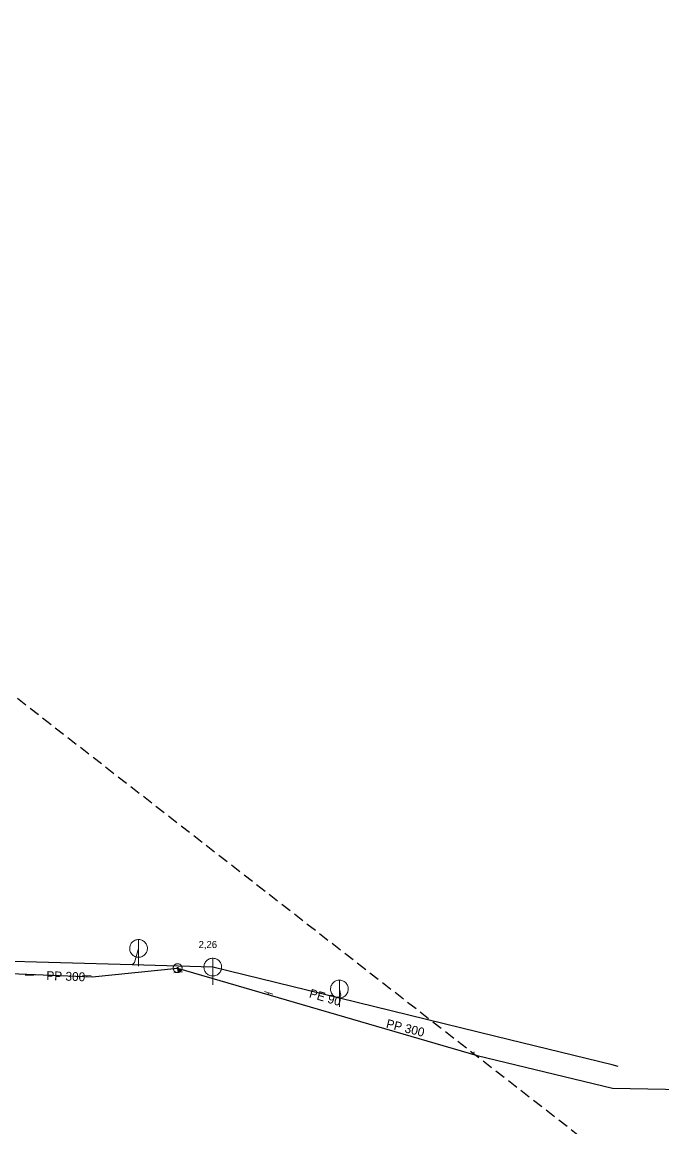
# Model space of a CAD drawing. Extents: x -683466 to -682479, y -996772 to -995963.
# Drawn here: x -683237.4 to -683165.2, y -996087.9 to -995963.2 of the extents above; entities that cross this region are included whole.
import ezdxf

# ---------------------------------------------------------------- set-up
doc = ezdxf.new("R2010")
doc.units = 0
doc.header["$LTSCALE"] = 0.4
doc.linetypes.add('MEDIUM_DASHED', pattern=[4.5, 3, -1.5])
doc.layers.add('1', color=7, linetype='Continuous')
for name, color, linetype, lineweight in [('11', 7, 'Continuous', 13), ('14', 7, 'Continuous', 25), ('17', 7, 'Continuous', 25), ('22', 7, 'Continuous', 13), ('34', 7, 'Continuous', 13), ('47', 7, 'Continuous', 13), ('63', 7, 'MEDIUM_DASHED', 25), ('9', 7, 'Continuous', 13)]:
    doc.layers.add(name, color=color, linetype=linetype, lineweight=lineweight)

msp = doc.modelspace()

# ---------------------------------------------------------------- linework, layer by layer
at = {"layer": '11'}
for points in [[(-683224.3, -996067.739), (-683224.741, -996069.322), (-683225.026, -996069.59)], [(-683201.629, -996072.32), (-683201.464, -996073), (-683201.638, -996073.349)]]:
    msp.add_lwpolyline(points, dxfattribs=at)
at = {"layer": '14', "lineweight": 13}
for p, q in [((-683236.581, -996070.672), (-683236.579, -996070.77)), ((-683230.13, -996070.936), (-683230.129, -996070.809)), ((-683209.68, -996072.941), (-683209.62, -996072.75)), ((-683186.522, -996079.702), (-683186.44, -996079.399))]:
    msp.add_line(p, q, dxfattribs=at)
at = {"layer": '14'}
for points in [[(-683215.92, -996069.85), (-683225.026, -996069.59), (-683241.213, -996069.127), (-683247.399, -996068.949)], [(-683170.17, -996081.059), (-683170.859, -996080.89), (-683183.962, -996077.681), (-683201.638, -996073.349), (-683215.92, -996069.85)]]:
    msp.add_lwpolyline(points, dxfattribs=at)
at = {"layer": '14', "lineweight": 13}
msp.add_lwpolyline([(-683219.888, -996069.96), (-683219.831, -996070.447), (-683219.681, -996070.181)], dxfattribs=at)
at = {"layer": '17'}
for points in [[(-683345.87, -996001.27), (-683340.96, -996022.3), (-683339.832, -996025.943), (-683304.056, -996053.017), (-683282.79, -996067.766), (-683274.905, -996069.189), (-683269.5, -996070.27), (-683248.91, -996070.167), (-683229.542, -996070.96), (-683219.888, -996069.96)], [(-683219.888, -996069.96), (-683186.097, -996079.826), (-683170.817, -996083.517), (-683164.824, -996083.636), (-683139.583, -996085.59), (-683125.156, -996084.857)]]:
    msp.add_lwpolyline(points, dxfattribs=at)
at = {"layer": '22'}
for p, q in [((-683224.3, -996069.739), (-683224.299, -996066.739)), ((-683215.92, -996071.85), (-683215.919, -996068.85)), ((-683201.629, -996074.32), (-683201.628, -996071.32))]:
    msp.add_line(p, q, dxfattribs=at)
for points in [[(-683223.3, -996067.739), (-683223.305, -996067.63), (-683223.323, -996067.522), (-683223.353, -996067.416), (-683223.393, -996067.315), (-683223.445, -996067.218), (-683223.507, -996067.128), (-683223.579, -996067.045), (-683223.659, -996066.971), (-683223.747, -996066.905), (-683223.841, -996066.85), (-683223.941, -996066.805), (-683224.046, -996066.772), (-683224.153, -996066.75), (-683224.262, -996066.74), (-683224.372, -996066.742), (-683224.48, -996066.756), (-683224.587, -996066.781), (-683224.69, -996066.818), (-683224.788, -996066.867), (-683224.88, -996066.925), (-683224.966, -996066.994), (-683225.043, -996067.071), (-683225.112, -996067.157), (-683225.171, -996067.249), (-683225.219, -996067.347), (-683225.256, -996067.45), (-683225.282, -996067.557), (-683225.296, -996067.665), (-683225.299, -996067.775), (-683225.289, -996067.884), (-683225.268, -996067.991), (-683225.234, -996068.095), (-683225.19, -996068.195), (-683225.135, -996068.29), (-683225.069, -996068.378), (-683224.995, -996068.458), (-683224.912, -996068.53), (-683224.822, -996068.592), (-683224.726, -996068.644), (-683224.624, -996068.685), (-683224.519, -996068.715), (-683224.411, -996068.733), (-683224.301, -996068.739), (-683224.192, -996068.733), (-683224.084, -996068.715), (-683223.979, -996068.686), (-683223.877, -996068.645), (-683223.78, -996068.593), (-683223.69, -996068.531), (-683223.607, -996068.46), (-683223.532, -996068.38), (-683223.467, -996068.292), (-683223.411, -996068.198), (-683223.367, -996068.098), (-683223.333, -996067.994), (-683223.311, -996067.886), (-683223.301, -996067.777)], [(-683214.92, -996069.85), (-683214.925, -996069.741), (-683214.943, -996069.633), (-683214.973, -996069.527), (-683215.013, -996069.426), (-683215.065, -996069.329), (-683215.127, -996069.239), (-683215.199, -996069.156), (-683215.279, -996069.082), (-683215.367, -996069.016), (-683215.461, -996068.961), (-683215.561, -996068.916), (-683215.666, -996068.883), (-683215.773, -996068.861), (-683215.882, -996068.851), (-683215.992, -996068.853), (-683216.1, -996068.867), (-683216.207, -996068.892), (-683216.31, -996068.929), (-683216.408, -996068.978), (-683216.5, -996069.036), (-683216.586, -996069.105), (-683216.663, -996069.182), (-683216.732, -996069.268), (-683216.791, -996069.36), (-683216.839, -996069.458), (-683216.876, -996069.561), (-683216.902, -996069.668), (-683216.916, -996069.776), (-683216.919, -996069.886), (-683216.909, -996069.995), (-683216.888, -996070.102), (-683216.854, -996070.206), (-683216.81, -996070.306), (-683216.755, -996070.401), (-683216.689, -996070.489), (-683216.615, -996070.569), (-683216.532, -996070.641), (-683216.442, -996070.703), (-683216.346, -996070.755), (-683216.244, -996070.796), (-683216.139, -996070.826), (-683216.031, -996070.844), (-683215.921, -996070.85), (-683215.812, -996070.844), (-683215.704, -996070.826), (-683215.599, -996070.797), (-683215.497, -996070.756), (-683215.4, -996070.704), (-683215.31, -996070.642), (-683215.227, -996070.571), (-683215.152, -996070.491), (-683215.087, -996070.403), (-683215.031, -996070.309), (-683214.987, -996070.209), (-683214.953, -996070.105), (-683214.931, -996069.997), (-683214.921, -996069.888)], [(-683200.629, -996072.32), (-683200.634, -996072.211), (-683200.652, -996072.103), (-683200.682, -996071.997), (-683200.722, -996071.896), (-683200.774, -996071.799), (-683200.836, -996071.709), (-683200.908, -996071.626), (-683200.988, -996071.552), (-683201.076, -996071.486), (-683201.17, -996071.431), (-683201.27, -996071.386), (-683201.375, -996071.353), (-683201.482, -996071.331), (-683201.591, -996071.321), (-683201.701, -996071.323), (-683201.809, -996071.337), (-683201.916, -996071.362), (-683202.019, -996071.399), (-683202.117, -996071.448), (-683202.209, -996071.506), (-683202.295, -996071.575), (-683202.372, -996071.652), (-683202.441, -996071.738), (-683202.5, -996071.83), (-683202.548, -996071.928), (-683202.585, -996072.031), (-683202.611, -996072.138), (-683202.625, -996072.246), (-683202.628, -996072.356), (-683202.618, -996072.465), (-683202.597, -996072.572), (-683202.563, -996072.676), (-683202.519, -996072.776), (-683202.464, -996072.871), (-683202.398, -996072.959), (-683202.324, -996073.039), (-683202.241, -996073.111), (-683202.151, -996073.173), (-683202.055, -996073.225), (-683201.953, -996073.266), (-683201.848, -996073.296), (-683201.74, -996073.314), (-683201.63, -996073.32), (-683201.521, -996073.314), (-683201.413, -996073.296), (-683201.308, -996073.267), (-683201.206, -996073.226), (-683201.109, -996073.174), (-683201.019, -996073.112), (-683200.936, -996073.041), (-683200.861, -996072.961), (-683200.796, -996072.873), (-683200.74, -996072.779), (-683200.696, -996072.679), (-683200.662, -996072.575), (-683200.64, -996072.467), (-683200.63, -996072.358)]]:
    msp.add_lwpolyline(points, close=True, dxfattribs=at)
at = {"layer": '34'}
for p, q in [((-683219.335, -996070.39), (-683220.328, -996070.504)), ((-683236.079, -996070.763), (-683237.078, -996070.775)), ((-683230.628, -996070.805), (-683229.629, -996070.813)), ((-683210.096, -996072.599), (-683209.143, -996072.901))]:
    msp.add_line(p, q, dxfattribs=at)
at = {"layer": '47'}
for points in [[(-683219.388, -996069.96), (-683219.391, -996069.907), (-683219.399, -996069.855), (-683219.413, -996069.806), (-683219.431, -996069.757), (-683219.455, -996069.71), (-683219.484, -996069.666), (-683219.517, -996069.625), (-683219.554, -996069.588), (-683219.594, -996069.556), (-683219.638, -996069.527), (-683219.685, -996069.502), (-683219.734, -996069.485), (-683219.784, -996069.471), (-683219.836, -996069.463), (-683219.888, -996069.46), (-683219.94, -996069.463), (-683219.992, -996069.471), (-683220.043, -996069.485), (-683220.091, -996069.502), (-683220.138, -996069.527), (-683220.182, -996069.556), (-683220.223, -996069.588), (-683220.26, -996069.625), (-683220.293, -996069.666), (-683220.321, -996069.71), (-683220.345, -996069.757), (-683220.364, -996069.806), (-683220.377, -996069.855), (-683220.385, -996069.907), (-683220.388, -996069.96), (-683220.385, -996070.012), (-683220.377, -996070.064), (-683220.364, -996070.115), (-683220.345, -996070.163), (-683220.321, -996070.21), (-683220.293, -996070.254), (-683220.26, -996070.294), (-683220.223, -996070.331), (-683220.182, -996070.365), (-683220.138, -996070.392), (-683220.091, -996070.417), (-683220.043, -996070.436), (-683219.992, -996070.448), (-683219.94, -996070.456), (-683219.888, -996070.46), (-683219.836, -996070.456), (-683219.784, -996070.448), (-683219.734, -996070.436), (-683219.685, -996070.417), (-683219.638, -996070.392), (-683219.594, -996070.365), (-683219.554, -996070.331), (-683219.517, -996070.294), (-683219.484, -996070.254), (-683219.455, -996070.21), (-683219.431, -996070.163), (-683219.413, -996070.115), (-683219.399, -996070.064), (-683219.391, -996070.012)], [(-683219.806, -996069.96), (-683219.806, -996069.951), (-683219.808, -996069.943), (-683219.81, -996069.934), (-683219.813, -996069.926), (-683219.817, -996069.919), (-683219.822, -996069.912), (-683219.827, -996069.904), (-683219.833, -996069.899), (-683219.84, -996069.894), (-683219.847, -996069.889), (-683219.855, -996069.885), (-683219.863, -996069.882), (-683219.871, -996069.88), (-683219.879, -996069.877), (-683219.888, -996069.877), (-683219.897, -996069.877), (-683219.905, -996069.88), (-683219.913, -996069.882), (-683219.921, -996069.885), (-683219.929, -996069.889), (-683219.936, -996069.894), (-683219.943, -996069.899), (-683219.949, -996069.904), (-683219.955, -996069.912), (-683219.959, -996069.919), (-683219.963, -996069.926), (-683219.966, -996069.934), (-683219.968, -996069.943), (-683219.97, -996069.951), (-683219.97, -996069.96), (-683219.97, -996069.968), (-683219.968, -996069.977), (-683219.966, -996069.985), (-683219.963, -996069.993), (-683219.959, -996070), (-683219.955, -996070.007), (-683219.949, -996070.015), (-683219.943, -996070.021), (-683219.936, -996070.027), (-683219.929, -996070.031), (-683219.921, -996070.034), (-683219.913, -996070.038), (-683219.905, -996070.039), (-683219.897, -996070.042), (-683219.888, -996070.042), (-683219.879, -996070.042), (-683219.871, -996070.039), (-683219.863, -996070.038), (-683219.855, -996070.034), (-683219.847, -996070.031), (-683219.84, -996070.027), (-683219.833, -996070.021), (-683219.827, -996070.015), (-683219.822, -996070.007), (-683219.817, -996070), (-683219.813, -996069.993), (-683219.81, -996069.985), (-683219.808, -996069.977), (-683219.806, -996069.968)]]:
    msp.add_lwpolyline(points, close=True, dxfattribs=at)
at = {"layer": '63'}
msp.add_lwpolyline([(-683425.281, -996021.839), (-683425.281, -996016.256), (-683425.281, -996016.256), (-683335.962, -995963.223), (-683335.962, -995963.223), (-682479.059, -996630.324), (-682479.059, -996630.324), (-682551.631, -996711.269), (-682551.631, -996711.269), (-683416.907, -996083.246), (-683416.907, -996083.246)], close=True, dxfattribs=at)
at = {"layer": '9'}
for points in [[(-683219.807, -996070.181), (-683219.807, -996070.194), (-683219.804, -996070.207), (-683219.802, -996070.22), (-683219.797, -996070.232), (-683219.791, -996070.244), (-683219.784, -996070.255), (-683219.776, -996070.265), (-683219.766, -996070.275), (-683219.755, -996070.283), (-683219.745, -996070.29), (-683219.733, -996070.296), (-683219.721, -996070.301), (-683219.708, -996070.304), (-683219.695, -996070.306), (-683219.682, -996070.308), (-683219.669, -996070.307), (-683219.656, -996070.305), (-683219.643, -996070.302), (-683219.63, -996070.297), (-683219.619, -996070.291), (-683219.608, -996070.284), (-683219.598, -996070.276), (-683219.588, -996070.266), (-683219.58, -996070.256), (-683219.573, -996070.245), (-683219.567, -996070.233), (-683219.562, -996070.221), (-683219.559, -996070.208), (-683219.557, -996070.195), (-683219.554, -996070.182), (-683219.556, -996070.169), (-683219.558, -996070.156), (-683219.561, -996070.143), (-683219.566, -996070.131), (-683219.571, -996070.119), (-683219.579, -996070.108), (-683219.587, -996070.098), (-683219.597, -996070.088), (-683219.607, -996070.08), (-683219.618, -996070.073), (-683219.63, -996070.067), (-683219.642, -996070.062), (-683219.655, -996070.059), (-683219.668, -996070.057), (-683219.681, -996070.056), (-683219.694, -996070.056), (-683219.706, -996070.058), (-683219.72, -996070.061), (-683219.732, -996070.066), (-683219.744, -996070.072), (-683219.755, -996070.079), (-683219.765, -996070.087), (-683219.775, -996070.097), (-683219.782, -996070.107), (-683219.79, -996070.118), (-683219.796, -996070.13), (-683219.801, -996070.142), (-683219.804, -996070.155), (-683219.806, -996070.168)], [(-683219.787, -996070.181), (-683219.788, -996070.192), (-683219.786, -996070.203), (-683219.782, -996070.214), (-683219.779, -996070.224), (-683219.774, -996070.234), (-683219.768, -996070.243), (-683219.761, -996070.252), (-683219.753, -996070.26), (-683219.744, -996070.267), (-683219.735, -996070.273), (-683219.725, -996070.278), (-683219.715, -996070.282), (-683219.704, -996070.285), (-683219.693, -996070.288), (-683219.682, -996070.288), (-683219.671, -996070.288), (-683219.66, -996070.286), (-683219.649, -996070.283), (-683219.639, -996070.279), (-683219.629, -996070.274), (-683219.62, -996070.268), (-683219.611, -996070.261), (-683219.603, -996070.253), (-683219.596, -996070.244), (-683219.59, -996070.235), (-683219.585, -996070.225), (-683219.581, -996070.215), (-683219.578, -996070.204), (-683219.576, -996070.193), (-683219.575, -996070.182), (-683219.575, -996070.171), (-683219.576, -996070.16), (-683219.58, -996070.149), (-683219.584, -996070.139), (-683219.589, -996070.129), (-683219.595, -996070.12), (-683219.602, -996070.111), (-683219.61, -996070.103), (-683219.619, -996070.096), (-683219.628, -996070.09), (-683219.638, -996070.085), (-683219.647, -996070.081), (-683219.659, -996070.078), (-683219.669, -996070.076), (-683219.681, -996070.076), (-683219.692, -996070.075), (-683219.703, -996070.077), (-683219.714, -996070.08), (-683219.723, -996070.084), (-683219.733, -996070.089), (-683219.743, -996070.095), (-683219.752, -996070.102), (-683219.76, -996070.11), (-683219.767, -996070.119), (-683219.772, -996070.128), (-683219.777, -996070.138), (-683219.782, -996070.148), (-683219.785, -996070.159), (-683219.787, -996070.17)], [(-683219.768, -996070.181), (-683219.768, -996070.19), (-683219.767, -996070.199), (-683219.764, -996070.208), (-683219.761, -996070.216), (-683219.757, -996070.224), (-683219.752, -996070.232), (-683219.745, -996070.239), (-683219.74, -996070.245), (-683219.733, -996070.251), (-683219.725, -996070.256), (-683219.717, -996070.26), (-683219.709, -996070.263), (-683219.7, -996070.266), (-683219.691, -996070.267), (-683219.682, -996070.269), (-683219.673, -996070.268), (-683219.664, -996070.267), (-683219.655, -996070.264), (-683219.647, -996070.261), (-683219.639, -996070.257), (-683219.63, -996070.252), (-683219.624, -996070.246), (-683219.618, -996070.24), (-683219.612, -996070.233), (-683219.607, -996070.225), (-683219.603, -996070.217), (-683219.6, -996070.209), (-683219.597, -996070.2), (-683219.596, -996070.191), (-683219.593, -996070.182), (-683219.595, -996070.173), (-683219.596, -996070.164), (-683219.598, -996070.155), (-683219.602, -996070.147), (-683219.606, -996070.139), (-683219.611, -996070.131), (-683219.617, -996070.124), (-683219.623, -996070.118), (-683219.63, -996070.112), (-683219.638, -996070.107), (-683219.646, -996070.103), (-683219.654, -996070.1), (-683219.663, -996070.097), (-683219.672, -996070.096), (-683219.681, -996070.095), (-683219.69, -996070.095), (-683219.699, -996070.096), (-683219.708, -996070.099), (-683219.716, -996070.102), (-683219.723, -996070.106), (-683219.732, -996070.111), (-683219.739, -996070.117), (-683219.745, -996070.123), (-683219.75, -996070.13), (-683219.755, -996070.138), (-683219.76, -996070.146), (-683219.763, -996070.154), (-683219.766, -996070.163), (-683219.767, -996070.172)], [(-683219.748, -996070.181), (-683219.748, -996070.188), (-683219.747, -996070.195), (-683219.745, -996070.202), (-683219.743, -996070.208), (-683219.74, -996070.214), (-683219.736, -996070.22), (-683219.732, -996070.226), (-683219.727, -996070.231), (-683219.721, -996070.235), (-683219.715, -996070.239), (-683219.709, -996070.242), (-683219.703, -996070.245), (-683219.696, -996070.246), (-683219.689, -996070.249), (-683219.682, -996070.249), (-683219.674, -996070.249), (-683219.668, -996070.247), (-683219.661, -996070.246), (-683219.655, -996070.243), (-683219.647, -996070.24), (-683219.643, -996070.236), (-683219.637, -996070.232), (-683219.632, -996070.227), (-683219.628, -996070.221), (-683219.624, -996070.215), (-683219.62, -996070.209), (-683219.618, -996070.203), (-683219.616, -996070.196), (-683219.615, -996070.189), (-683219.614, -996070.182), (-683219.614, -996070.175), (-683219.615, -996070.168), (-683219.617, -996070.161), (-683219.62, -996070.155), (-683219.623, -996070.148), (-683219.627, -996070.143), (-683219.63, -996070.137), (-683219.636, -996070.132), (-683219.642, -996070.128), (-683219.647, -996070.124), (-683219.654, -996070.121), (-683219.66, -996070.118), (-683219.667, -996070.116), (-683219.674, -996070.115), (-683219.681, -996070.115), (-683219.688, -996070.115), (-683219.695, -996070.115), (-683219.701, -996070.117), (-683219.708, -996070.12), (-683219.714, -996070.123), (-683219.72, -996070.127), (-683219.726, -996070.131), (-683219.731, -996070.136), (-683219.735, -996070.142), (-683219.739, -996070.147), (-683219.742, -996070.154), (-683219.745, -996070.16), (-683219.745, -996070.167), (-683219.748, -996070.174)], [(-683219.728, -996070.181), (-683219.728, -996070.186), (-683219.728, -996070.191), (-683219.727, -996070.196), (-683219.725, -996070.2), (-683219.723, -996070.205), (-683219.72, -996070.209), (-683219.717, -996070.212), (-683219.713, -996070.216), (-683219.71, -996070.219), (-683219.706, -996070.222), (-683219.701, -996070.224), (-683219.696, -996070.226), (-683219.692, -996070.227), (-683219.687, -996070.229), (-683219.682, -996070.229), (-683219.677, -996070.229), (-683219.672, -996070.228), (-683219.667, -996070.227), (-683219.663, -996070.225), (-683219.657, -996070.223), (-683219.654, -996070.22), (-683219.65, -996070.217), (-683219.647, -996070.213), (-683219.644, -996070.21), (-683219.641, -996070.206), (-683219.639, -996070.201), (-683219.637, -996070.197), (-683219.636, -996070.192), (-683219.635, -996070.187), (-683219.634, -996070.182), (-683219.634, -996070.177), (-683219.635, -996070.172), (-683219.636, -996070.167), (-683219.638, -996070.163), (-683219.64, -996070.158), (-683219.643, -996070.154), (-683219.646, -996070.15), (-683219.649, -996070.147), (-683219.652, -996070.144), (-683219.657, -996070.141), (-683219.662, -996070.139), (-683219.666, -996070.137), (-683219.671, -996070.136), (-683219.676, -996070.135), (-683219.681, -996070.135), (-683219.686, -996070.135), (-683219.691, -996070.136), (-683219.696, -996070.136), (-683219.7, -996070.138), (-683219.705, -996070.14), (-683219.709, -996070.143), (-683219.712, -996070.146), (-683219.716, -996070.149), (-683219.718, -996070.153), (-683219.722, -996070.157), (-683219.723, -996070.162), (-683219.726, -996070.166), (-683219.727, -996070.171), (-683219.728, -996070.176)], [(-683219.708, -996070.181), (-683219.708, -996070.184), (-683219.709, -996070.187), (-683219.708, -996070.189), (-683219.706, -996070.192), (-683219.706, -996070.195), (-683219.704, -996070.197), (-683219.701, -996070.199), (-683219.7, -996070.201), (-683219.698, -996070.203), (-683219.696, -996070.205), (-683219.693, -996070.207), (-683219.69, -996070.208), (-683219.688, -996070.208), (-683219.684, -996070.209), (-683219.682, -996070.209), (-683219.679, -996070.209), (-683219.676, -996070.209), (-683219.673, -996070.208), (-683219.671, -996070.207), (-683219.668, -996070.206), (-683219.666, -996070.204), (-683219.663, -996070.202), (-683219.661, -996070.2), (-683219.66, -996070.198), (-683219.657, -996070.196), (-683219.657, -996070.193), (-683219.655, -996070.19), (-683219.655, -996070.188), (-683219.654, -996070.185), (-683219.652, -996070.182), (-683219.654, -996070.179), (-683219.654, -996070.176), (-683219.655, -996070.173), (-683219.656, -996070.171), (-683219.657, -996070.168), (-683219.659, -996070.166), (-683219.66, -996070.163), (-683219.662, -996070.161), (-683219.665, -996070.16), (-683219.667, -996070.158), (-683219.669, -996070.157), (-683219.672, -996070.156), (-683219.674, -996070.155), (-683219.678, -996070.155), (-683219.681, -996070.154), (-683219.684, -996070.155), (-683219.687, -996070.154), (-683219.689, -996070.156), (-683219.692, -996070.156), (-683219.695, -996070.157), (-683219.696, -996070.159), (-683219.699, -996070.16), (-683219.701, -996070.162), (-683219.703, -996070.165), (-683219.705, -996070.167), (-683219.706, -996070.17), (-683219.706, -996070.172), (-683219.708, -996070.175), (-683219.708, -996070.178)], [(-683219.689, -996070.181), (-683219.689, -996070.183), (-683219.689, -996070.183), (-683219.688, -996070.183), (-683219.688, -996070.185), (-683219.689, -996070.186), (-683219.687, -996070.186), (-683219.687, -996070.186), (-683219.687, -996070.188), (-683219.687, -996070.188), (-683219.686, -996070.189), (-683219.684, -996070.189), (-683219.684, -996070.189), (-683219.684, -996070.19), (-683219.682, -996070.19), (-683219.682, -996070.19), (-683219.681, -996070.19), (-683219.679, -996070.19), (-683219.679, -996070.189), (-683219.679, -996070.189), (-683219.677, -996070.189), (-683219.677, -996070.188), (-683219.677, -996070.188), (-683219.676, -996070.187), (-683219.676, -996070.187), (-683219.674, -996070.186), (-683219.674, -996070.185), (-683219.673, -996070.184), (-683219.673, -996070.184), (-683219.673, -996070.183), (-683219.673, -996070.182), (-683219.673, -996070.181), (-683219.673, -996070.18), (-683219.673, -996070.18), (-683219.674, -996070.179), (-683219.674, -996070.178), (-683219.674, -996070.177), (-683219.674, -996070.177), (-683219.676, -996070.176), (-683219.676, -996070.176), (-683219.677, -996070.175), (-683219.678, -996070.175), (-683219.679, -996070.174), (-683219.679, -996070.174), (-683219.679, -996070.174), (-683219.681, -996070.174), (-683219.682, -996070.174), (-683219.683, -996070.174), (-683219.683, -996070.174), (-683219.684, -996070.175), (-683219.684, -996070.174), (-683219.686, -996070.176), (-683219.686, -996070.176), (-683219.687, -996070.176), (-683219.687, -996070.176), (-683219.688, -996070.178), (-683219.688, -996070.179), (-683219.688, -996070.18), (-683219.689, -996070.18), (-683219.689, -996070.181)]]:
    msp.add_lwpolyline(points, close=True, dxfattribs=at)

# ---------------------------------------------------------------- texts
at = {"layer": '1'}
msp.add_text('2,26', height=0.8, dxfattribs=at).set_placement((-683217.519, -996067.697))
for s, rotation, p in [('PP 300', 358, (-683234.715, -996071.298)), ('PE 90 ', 344, (-683205.115, -996073.246)), ('PP 300', 346, (-683196.43, -996076.669))]:
    msp.add_text(s, height=1, rotation=rotation, dxfattribs=at).set_placement(p)

doc.saveas('drawing.dxf')
